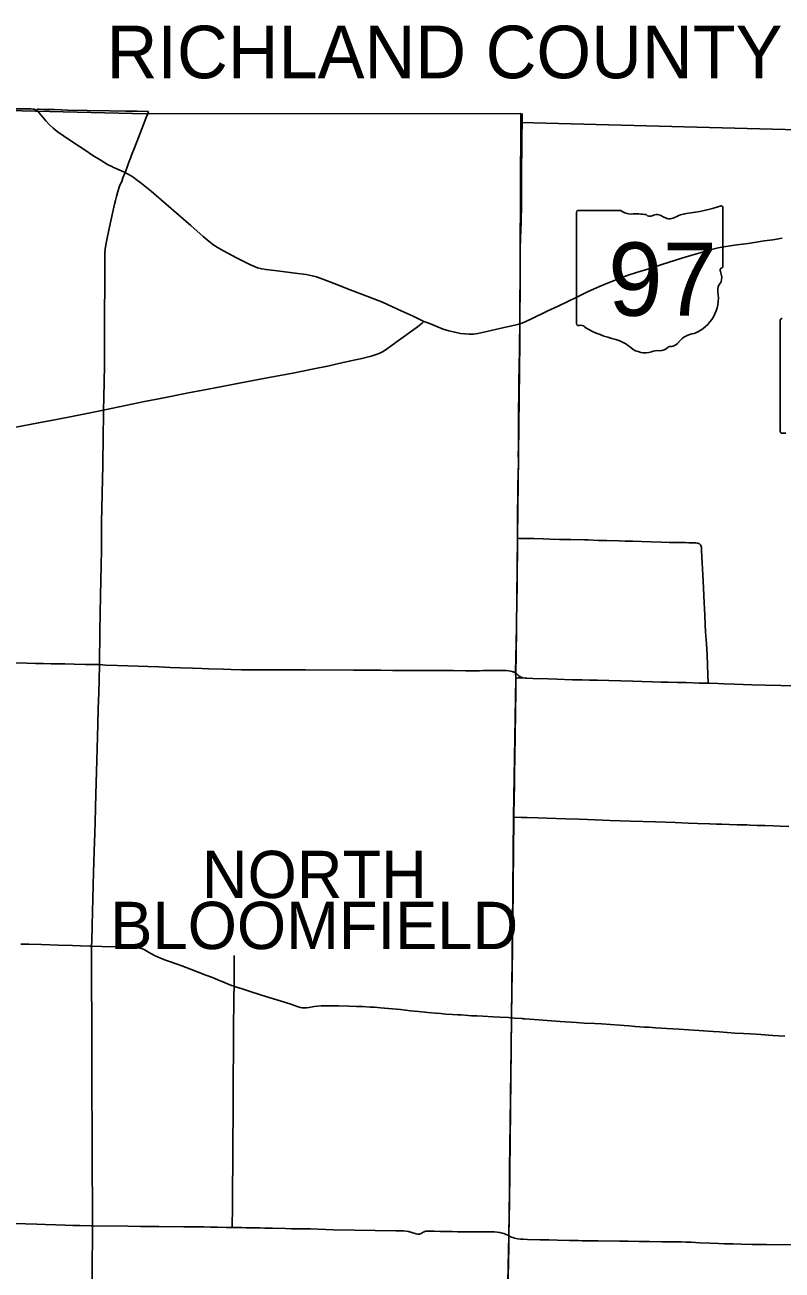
# Model space of a CAD drawing. Extents: x 1815539 to 1947826, y 273303 to 993194.
# Drawn here: x 1906602 to 1921002, y 965571 to 989247 of the extents above; entities that cross this region are included whole.
import ezdxf

# ---------------------------------------------------------------- set-up
doc = ezdxf.new("R2010")
doc.units = 0
for name, color, linetype in [('GM_X_Adjacent_County_Text', 7, 'Continuous'), ('GM_X_County', 7, 'Continuous'), ('GM_X_County_Road', 7, 'Continuous'), ('GM_X_State_Route', 7, 'Continuous'), ('GM_X_Township', 7, 'Continuous'), ('GM_X_Township_Road', 7, 'Continuous'), ('GM_X_Township_Text', 7, 'Continuous'), ('SC_Shading3', 7, 'Continuous')]:
    doc.layers.add(name, color=color, linetype=linetype)

msp = doc.modelspace()

# ---------------------------------------------------------------- linework, layer by layer
at = {"layer": 'GM_X_County'}
msp.add_lwpolyline([(1905517, 987636), (1906801, 987606), (1908915, 987558), (1916031, 987559), (1916031, 987390), (1922491, 987223), (1925127, 987155), (1933106, 986948), (1933172, 983252), (1933307, 978234), (1933364, 976428), (1933485, 971181), (1929986, 971246), (1928265, 971283), (1928303, 970087), (1928288, 969028), (1928289, 968947), (1928357, 965797), (1928425, 962614)], dxfattribs=at)
at = {"layer": 'GM_X_County_Road'}
for points in [[(1916057, 987391), (1916059, 987456), (1916058, 987561)], [(1916016, 983565), (1916015, 983766), (1916018, 984176), (1916019, 984389), (1916021, 984487), (1916021, 984635), (1916022, 984733), (1916023, 984848), (1916024, 984995), (1916029, 985191), (1916040, 985504), (1916044, 985833), (1916048, 986060), (1916047, 986374), (1916047, 986521), (1916052, 986898), (1916054, 987029), (1916055, 987160), (1916057, 987357), (1916057, 987391)], [(1908451, 986297), (1908467, 986336), (1908506, 986441)], [(1908323, 985905), (1908342, 985987), (1908369, 986081), (1908400, 986178), (1908449, 986290), (1908451, 986297)], [(1908294, 985782), (1908314, 985866), (1908323, 985905)], [(1908100, 981923), (1908104, 982164), (1908107, 982459), (1908113, 982770), (1908115, 982983), (1908115, 983131), (1908113, 983196), (1908114, 983295), (1908118, 983820), (1908121, 984246), (1908124, 984902), (1908129, 984984), (1908141, 985065), (1908166, 985193), (1908225, 985464), (1908280, 985721), (1908294, 985782)], [(1915971, 979485), (1915971, 979488), (1915972, 980045), (1915975, 980209), (1915978, 980422), (1915978, 980554), (1915981, 980652), (1915983, 980734), (1915986, 980832), (1915986, 980897), (1915986, 980963), (1915985, 981078), (1915986, 981209), (1915988, 981340), (1915988, 981684), (1915990, 981865), (1915994, 982274), (1915997, 982455), (1916002, 982766), (1916007, 983061), (1916011, 983225), (1916016, 983520), (1916016, 983565)], [(1908018, 977084), (1908029, 977718), (1908035, 978063), (1908043, 978391), (1908051, 978981), (1908056, 979244), (1908058, 979523), (1908062, 979801), (1908067, 980047), (1908073, 980343), (1908083, 980868), (1908092, 981442), (1908098, 981819), (1908100, 981923)], [(1915937, 976924), (1915937, 976948), (1915944, 977243), (1915946, 977391), (1915950, 977637), (1915952, 977817), (1915953, 977899), (1915953, 977997), (1915955, 978145), (1915959, 978390), (1915961, 978472), (1915961, 978571), (1915962, 978685), (1915963, 978767), (1915965, 978915), (1915968, 979177), (1915970, 979357), (1915971, 979485)], [(1906165, 977125), (1906361, 977120), (1906640, 977112), (1906804, 977107), (1906951, 977103), (1907099, 977100), (1907361, 977095), (1907542, 977091), (1907755, 977086), (1907985, 977084), (1908018, 977084)], [(1907872, 971728), (1907873, 971831), (1907880, 972126), (1907892, 972634), (1907901, 972897), (1907907, 973126), (1907920, 973536), (1907931, 973880), (1907937, 974094), (1907951, 974618), (1907969, 975258), (1907988, 975947), (1907997, 976242), (1908006, 976554), (1908013, 976783), (1908018, 977084)], [(1908018, 977084), (1908136, 977075), (1908365, 977068), (1908758, 977054), (1908938, 977046), (1909151, 977038), (1909364, 977030), (1909561, 977025), (1909790, 977016), (1909970, 977009), (1910101, 977006), (1910380, 976995), (1910527, 976990), (1910724, 976986), (1911084, 976983), (1911936, 976981), (1912852, 976976), (1913371, 976976), (1913591, 976973), (1913870, 976973), (1914017, 976974), (1914213, 976971), (1914328, 976971), (1914558, 976970), (1914754, 976969), (1914984, 976968), (1915098, 976968), (1915246, 976968), (1915311, 976969), (1915409, 976970), (1915655, 976970), (1915754, 976969), (1915803, 976965), (1915835, 976961), (1915867, 976954), (1915882, 976949), (1915897, 976943), (1915937, 976924)], [(1915937, 976924), (1915982, 976881), (1915991, 976873), (1916018, 976855), (1916033, 976847), (1916049, 976841), (1916065, 976836), (1916069, 976835)], [(1915938, 976819), (1915939, 976850), (1915937, 976924)], [(1915901, 974182), (1915901, 974220), (1915906, 974554), (1915910, 974783), (1915913, 974980), (1915919, 975357), (1915924, 975702), (1915931, 976194), (1915938, 976554), (1915939, 976751), (1915938, 976819)], [(1915938, 976819), (1915960, 976825), (1915983, 976830), (1916015, 976832), (1916037, 976834), (1916069, 976835)], [(1916069, 976835), (1916081, 976832), (1916114, 976826), (1916146, 976823), (1916261, 976818), (1916557, 976813), (1916720, 976807), (1917016, 976796), (1917199, 976793), (1917342, 976790), (1917491, 976789), (1917704, 976781), (1918163, 976767), (1918343, 976764), (1918540, 976757), (1918704, 976752), (1918834, 976748), (1919014, 976746), (1919180, 976740), (1919423, 976731), (1919598, 976728)], [(1919598, 976728), (1919624, 976728), (1919785, 976722), (1919899, 976717), (1920096, 976710), (1920424, 976701), (1920686, 976694), (1920981, 976685), (1921211, 976677), (1921621, 976666), (1921801, 976663), (1922129, 976658), (1922259, 976656), (1922734, 976645), (1922831, 976643), (1922947, 976639)], [(1915901, 974182), (1916055, 974178), (1916153, 974174), (1916366, 974167), (1916530, 974161), (1916890, 974149), (1917136, 974143), (1917300, 974137), (1917447, 974131), (1917594, 974125), (1917725, 974121), (1918118, 974105), (1918593, 974091), (1918970, 974079), (1919216, 974070), (1919396, 974063), (1919621, 974056)], [(1919621, 974056), (1919625, 974056), (1919756, 974051), (1919854, 974049), (1920002, 974044), (1920149, 974038), (1920264, 974035), (1920329, 974034), (1920395, 974032), (1920526, 974027), (1920673, 974024), (1920837, 974020), (1920968, 974014), (1921132, 974008)], [(1907889, 966413), (1907887, 966550), (1907887, 966747), (1907886, 967009), (1907882, 967305), (1907881, 967550), (1907881, 967731), (1907882, 967911), (1907881, 968239), (1907879, 968419), (1907878, 968764), (1907875, 968977), (1907875, 969207), (1907874, 969485), (1907873, 969617), (1907875, 969813), (1907875, 970207), (1907873, 970584), (1907872, 970780), (1907870, 970928), (1907870, 971092), (1907871, 971223), (1907870, 971387), (1907871, 971567), (1907871, 971666), (1907872, 971728)], [(1906435, 966459), (1906616, 966452), (1906829, 966442), (1906993, 966437), (1907189, 966431), (1907369, 966425), (1907517, 966421), (1907648, 966418), (1907862, 966413), (1907889, 966413)], [(1907879, 965387), (1907880, 965633), (1907882, 965813), (1907887, 966075), (1907888, 966174), (1907889, 966305), (1907889, 966370), (1907889, 966413)], [(1907889, 966413), (1908561, 966405), (1908807, 966401), (1909152, 966398), (1909627, 966392), (1909824, 966390), (1910004, 966390), (1910134, 966389), (1910264, 966386), (1910428, 966382), (1910544, 966382)], [(1910544, 966382), (1910592, 966381), (1910723, 966378), (1910805, 966376), (1910887, 966374), (1911067, 966371), (1911165, 966368), (1911313, 966365), (1911559, 966359), (1911673, 966356), (1911788, 966355), (1912034, 966353), (1912474, 966339), (1912869, 966331), (1913655, 966320), (1913753, 966319), (1913802, 966316), (1913851, 966311), (1913899, 966302), (1913963, 966285), (1914042, 966263), (1914074, 966256), (1914090, 966255), (1914106, 966256), (1914122, 966260), (1914137, 966267), (1914178, 966294), (1914193, 966301), (1914208, 966307), (1914224, 966310), (1914240, 966312), (1914289, 966313), (1914387, 966309), (1914502, 966306), (1914617, 966303), (1914731, 966302), (1914830, 966301), (1915010, 966299), (1915174, 966298), (1915321, 966299), (1915469, 966299), (1915534, 966296), (1915583, 966292), (1915632, 966285), (1915680, 966274), (1915711, 966265), (1915757, 966247), (1915770, 966242), (1915789, 966232), (1915807, 966222)], [(1915807, 966222), (1915822, 966213), (1915838, 966203), (1915859, 966195), (1915881, 966188), (1915913, 966179), (1915978, 966167), (1916027, 966160), (1916076, 966156), (1916158, 966153), (1916404, 966148), (1916568, 966143), (1916732, 966140), (1916962, 966135), (1917125, 966131), (1917199, 966129)], [(1917199, 966129), (1917240, 966129), (1917504, 966127), (1917911, 966121), (1918075, 966119), (1918276, 966117), (1918478, 966114), (1918714, 966110), (1918845, 966109), (1918894, 966108), (1918943, 966108), (1919091, 966106), (1919172, 966102), (1919271, 966099), (1919435, 966092), (1919631, 966082), (1919795, 966075), (1919909, 966072), (1920073, 966067), (1920221, 966064), (1920434, 966060), (1920708, 966058), (1921206, 966052)]]:
    msp.add_lwpolyline(points, dxfattribs=at)
at = {"layer": 'GM_X_State_Route'}
for points in [[(1905542, 987658), (1905547, 987658), (1905682, 987656), (1906289, 987652), (1906601, 987650), (1906712, 987648), (1906761, 987646), (1906773, 987645), (1906793, 987639), (1906809, 987633), (1906820, 987627)], [(1906820, 987627), (1906831, 987619), (1906841, 987610), (1906858, 987593), (1906873, 987575), (1907001, 987423), (1907079, 987339), (1907139, 987282), (1907216, 987221), (1907337, 987136), (1907512, 987015), (1907746, 986863), (1907897, 986766), (1908035, 986678), (1908175, 986592), (1908266, 986548), (1908288, 986538), (1908307, 986530), (1908336, 986518), (1908366, 986505), (1908454, 986466), (1908506, 986441), (1908542, 986423), (1908613, 986384), (1908654, 986357), (1908720, 986310), (1908811, 986240), (1909001, 986083), (1909290, 985840), (1909526, 985637), (1909761, 985432), (1909993, 985225), (1910106, 985129), (1910198, 985060), (1910280, 985006), (1910380, 984948), (1910628, 984819), (1910891, 984684), (1910966, 984650), (1911028, 984628), (1911108, 984608), (1911189, 984594), (1911450, 984563), (1911743, 984528), (1911954, 984500), (1912067, 984478), (1912145, 984456), (1912268, 984410), (1912482, 984328), (1912789, 984212), (1913158, 984073), (1913401, 983974), (1913595, 983886), (1913760, 983812), (1913983, 983709), (1914192, 983609), (1914284, 983573), (1914435, 983509), (1914556, 983463), (1914665, 983429), (1914777, 983402), (1914889, 983380), (1914970, 983370), (1915052, 983365), (1915133, 983368), (1915214, 983378), (1915390, 983418), (1915661, 983483), (1915918, 983537), (1915997, 983558), (1916016, 983565), (1916073, 983585), (1916222, 983654), (1916549, 983807), (1916741, 983899), (1917110, 984078), (1917303, 984169), (1917482, 984252), (1917648, 984323), (1917923, 984431), (1918077, 984486), (1918234, 984536), (1918468, 984610), (1918717, 984694), (1919094, 984809), (1919329, 984879), (1919534, 984939), (1919660, 984975), (1919788, 985007), (1919933, 985035), (1920144, 985064), (1920355, 985093), (1920664, 985138), (1920826, 985162), (1921004, 985192)], [(1906397, 981589), (1906864, 981680), (1907202, 981746), (1907557, 981816), (1908100, 981923), (1908120, 981927), (1908393, 981985), (1908875, 982083), (1909181, 982144), (1909712, 982248), (1909986, 982301), (1910325, 982366), (1910647, 982427), (1911211, 982535), (1911695, 982626), (1912065, 982698), (1912386, 982767), (1912488, 982789), (1912771, 982850), (1913011, 982903), (1913186, 982947), (1913280, 982977), (1913355, 983008), (1913413, 983039), (1913495, 983092), (1913708, 983245), (1914040, 983486), (1914155, 983578), (1914192, 983609)]]:
    msp.add_lwpolyline(points, dxfattribs=at)
at = {"layer": 'GM_X_Township'}
msp.add_lwpolyline([(1916031, 987559), (1916031, 987390), (1916016, 983574), (1916012, 983206), (1915968, 979502), (1915954, 977797), (1915930, 976934), (1915938, 976821), (1915894, 974189), (1915874, 972112), (1915857, 970374), (1915816, 966860), (1915806, 966233), (1915788, 965343), (1915744, 960965)], dxfattribs=at)
at = {"layer": 'GM_X_Township_Road'}
for points in [[(1906820, 987627), (1906832, 987636), (1906840, 987640), (1906850, 987642), (1906871, 987643), (1906969, 987640), (1907165, 987635), (1907298, 987630), (1907413, 987628), (1907789, 987622), (1908213, 987615), (1908522, 987609), (1908738, 987605), (1908954, 987601)], [(1908506, 986441), (1908547, 986544), (1908581, 986636), (1908609, 986711), (1908632, 986772), (1908684, 986909), (1908762, 987107), (1908856, 987350), (1908909, 987488), (1908933, 987546), (1908954, 987601)], [(1915971, 979485), (1916000, 979484), (1916082, 979481), (1916163, 979480), (1916278, 979478), (1916458, 979473), (1916590, 979469), (1916770, 979464), (1916885, 979461), (1916983, 979459), (1917246, 979454), (1917311, 979453), (1917508, 979446), (1917672, 979441), (1917901, 979435), (1918019, 979433), (1918164, 979428), (1918328, 979423), (1918509, 979417), (1918706, 979412), (1918854, 979408), (1918985, 979406), (1919166, 979402), (1919231, 979401), (1919280, 979399), (1919363, 979397), (1919395, 979393), (1919411, 979389), (1919426, 979383), (1919440, 979374), (1919451, 979362), (1919459, 979348), (1919464, 979332), (1919467, 979316), (1919470, 979250), (1919479, 979020), (1919492, 978791), (1919505, 978545), (1919520, 978249), (1919525, 978151), (1919533, 978020), (1919542, 977839), (1919548, 977708), (1919563, 977479), (1919574, 977265), (1919592, 976888), (1919598, 976728)], [(1915876, 971659), (1915877, 971687), (1915878, 971868), (1915882, 972048), (1915882, 972147), (1915882, 972311), (1915884, 972442), (1915886, 972622), (1915890, 972950), (1915893, 973492), (1915895, 973754), (1915898, 973934), (1915899, 974033), (1915900, 974115), (1915901, 974182)], [(1906526, 971770), (1906674, 971765), (1906920, 971759), (1907232, 971749), (1907510, 971740), (1907658, 971735), (1907838, 971729), (1907872, 971728)], [(1907872, 971728), (1908068, 971724), (1908412, 971718), (1908609, 971714), (1908675, 971711), (1908724, 971707), (1908756, 971702), (1908788, 971694), (1908819, 971685), (1908850, 971673), (1908880, 971659), (1908909, 971644), (1909007, 971584), (1909065, 971553), (1909124, 971525), (1909184, 971500), (1909276, 971464), (1909353, 971436), (1909477, 971393), (1909585, 971354), (1909754, 971290), (1910045, 971180), (1910168, 971132), (1910274, 971089), (1910411, 971033), (1910533, 970985), (1910579, 970968)], [(1910579, 970968), (1910579, 970976), (1910579, 971018), (1910580, 971083), (1910580, 971132), (1910581, 971206), (1910582, 971353), (1910583, 971435), (1910583, 971551)], [(1915857, 970366), (1915857, 970443), (1915858, 970525), (1915861, 970721), (1915862, 970819), (1915864, 970918), (1915865, 971000), (1915867, 971081), (1915869, 971196), (1915869, 971261), (1915869, 971343), (1915875, 971589), (1915876, 971659)], [(1910544, 966382), (1910545, 966404), (1910546, 966490), (1910550, 966671), (1910551, 966811), (1910552, 966910), (1910553, 967177), (1910555, 967555), (1910555, 967702), (1910555, 967949), (1910557, 968129), (1910560, 968425), (1910561, 968606), (1910562, 968739), (1910562, 968815), (1910563, 968910), (1910563, 968995), (1910563, 969061), (1910564, 969121), (1910564, 969186), (1910565, 969256), (1910566, 969453), (1910567, 969519), (1910568, 969552), (1910570, 969633), (1910571, 969696), (1910572, 969748), (1910572, 969797), (1910572, 969961), (1910571, 970043), (1910572, 970191), (1910577, 970684), (1910578, 970815), (1910579, 970926), (1910579, 970968)], [(1910579, 970968), (1910610, 970956), (1910735, 970917), (1910923, 970858), (1911204, 970768), (1911455, 970689), (1911658, 970624), (1911798, 970578), (1911846, 970566), (1911878, 970560), (1911910, 970557), (1911960, 970559), (1912009, 970564), (1912106, 970580), (1912171, 970589), (1912236, 970595), (1912302, 970597), (1912449, 970596), (1912564, 970593), (1912761, 970588), (1912908, 970583), (1913023, 970580), (1913170, 970573), (1913252, 970568), (1913367, 970560), (1913514, 970546), (1913742, 970523), (1913938, 970503), (1914085, 970488), (1914264, 970470), (1914412, 970455), (1914509, 970447), (1914557, 970443), (1914606, 970439), (1914736, 970431), (1914834, 970425), (1914900, 970421), (1915030, 970412), (1915096, 970408), (1915194, 970403), (1915309, 970398), (1915505, 970387), (1915636, 970381), (1915799, 970371), (1915857, 970366)], [(1915807, 966222), (1915806, 966230), (1915806, 966361), (1915809, 966509), (1915811, 966689), (1915814, 966820), (1915816, 966935), (1915818, 967131), (1915818, 967328), (1915819, 967426), (1915820, 967655), (1915823, 967787), (1915827, 968049), (1915829, 968262), (1915832, 968426), (1915833, 968524), (1915835, 968721), (1915838, 968885), (1915839, 969049), (1915841, 969213), (1915844, 969459), (1915848, 969656), (1915850, 969836), (1915852, 970049), (1915854, 970148), (1915857, 970279), (1915858, 970361), (1915857, 970366)], [(1915857, 970366), (1915913, 970363), (1916060, 970352), (1916076, 970350), (1916109, 970347), (1916289, 970334), (1916781, 970300), (1917092, 970278), (1917239, 970268), (1917435, 970257), (1917567, 970250), (1917910, 970226), (1918090, 970212), (1918205, 970205), (1918384, 970192), (1918466, 970187), (1918597, 970179), (1918810, 970164), (1919039, 970152), (1919219, 970138), (1919416, 970124), (1919694, 970105), (1919809, 970098), (1919956, 970088), (1920103, 970078), (1920267, 970067), (1920398, 970060), (1920595, 970048), (1920824, 970032), (1921053, 970018)], [(1915790, 965307), (1915790, 965312), (1915794, 965542), (1915796, 965607), (1915797, 965673), (1915798, 965754), (1915803, 965968), (1915807, 966132), (1915807, 966222)]]:
    msp.add_lwpolyline(points, dxfattribs=at)
at = {"layer": 'SC_Shading3'}
for p, q in [((1917093, 985681), (1917093, 983568)), ((1917936, 985717), (1917120, 985717)), ((1919877, 984664), (1919877, 985770)), ((1919877, 984665), (1919877, 984664)), ((1920968, 983631), (1920968, 981517))]:
    msp.add_line(p, q, dxfattribs=at)
for centre, radius, start, end in [((1917125, 985686), 32.3, 98.1301, 188.1301), ((1918130, 985963), 313, 231.6195, 271.1119), ((1918234, 984531), 1123, 80.4867, 94.9883), ((1918489, 985697), 90.3, 219.7921, 297.1024), ((1918621, 985452), 188, 54.4667, 119.1411), ((1919262, 985072), 594, 97.3462, 120.7689), ((1918885, 988599), 2953, 275.8445, 288.9065), ((1919846, 985774), 31, 351.8621, 97.738), ((1918863, 985787), 226, 233.8562, 294.8282), ((1919870, 984583), 48, 107.944, 210.337), ((1919565, 984443), 288, 340.033, 23.6496), ((1919844, 984660), 33.2, 289.6038, 7.7341), ((1919988, 984202), 210, 136.8065, 186.9296), ((1919051, 984061), 739, 292.3089, 8.9858), ((1917125, 983563), 32.5, 171.9584, 258.3066), ((1917130, 983779), 248, 267.339, 280.6039), ((1917181, 983446), 89.5, 29.7484, 93.2717), ((1918311, 985345), 2132, 240.4129, 257.1985), ((1919362, 982974), 404, 94.4031, 142.5768), ((1917676, 982618), 667, 47.1842, 75.836), ((1918397, 983435), 423, 230.7004, 286.2918), ((1918642, 982705), 348, 85.6951, 111.2099), ((1918673, 983277), 226, 268.777, 315.5493), ((1918877, 983072), 63.5, 65.7517, 132.6484), ((1918850, 983363), 239, 282.8732, 323.2771)]:
    msp.add_arc(centre, radius, start, end, dxfattribs=at)
for centre, major_axis, start_param, end_param in [((1921008, 983635), (40.3, 0), 1.712693, 3.28349), ((1921008, 981513), (40.7, 0), 3.00124, 4.508301), ((1921014, 981729), (310, 0), 4.665946, 4.897461)]:
    msp.add_ellipse(centre, major_axis=major_axis, ratio=0.8, start_param=start_param, end_param=end_param, dxfattribs=at)

# ---------------------------------------------------------------- texts
at = {"layer": 'GM_X_Adjacent_County_Text'}
msp.add_text('RICHLAND COUNTY', height=1000, dxfattribs=at).set_placement((1908157, 988232))
at = {"layer": 'GM_X_Township_Text'}
for s, p in [('NORTH', (1909968, 972643)), ('BLOOMFIELD', (1908226, 971674))]:
    msp.add_text(s, height=900, rotation=0, dxfattribs=at).set_placement(p)
at = {"layer": 'SC_Shading3'}
msp.add_text('97', height=1392.2, dxfattribs=at).set_placement((1917694, 983717))

doc.saveas('drawing.dxf')
